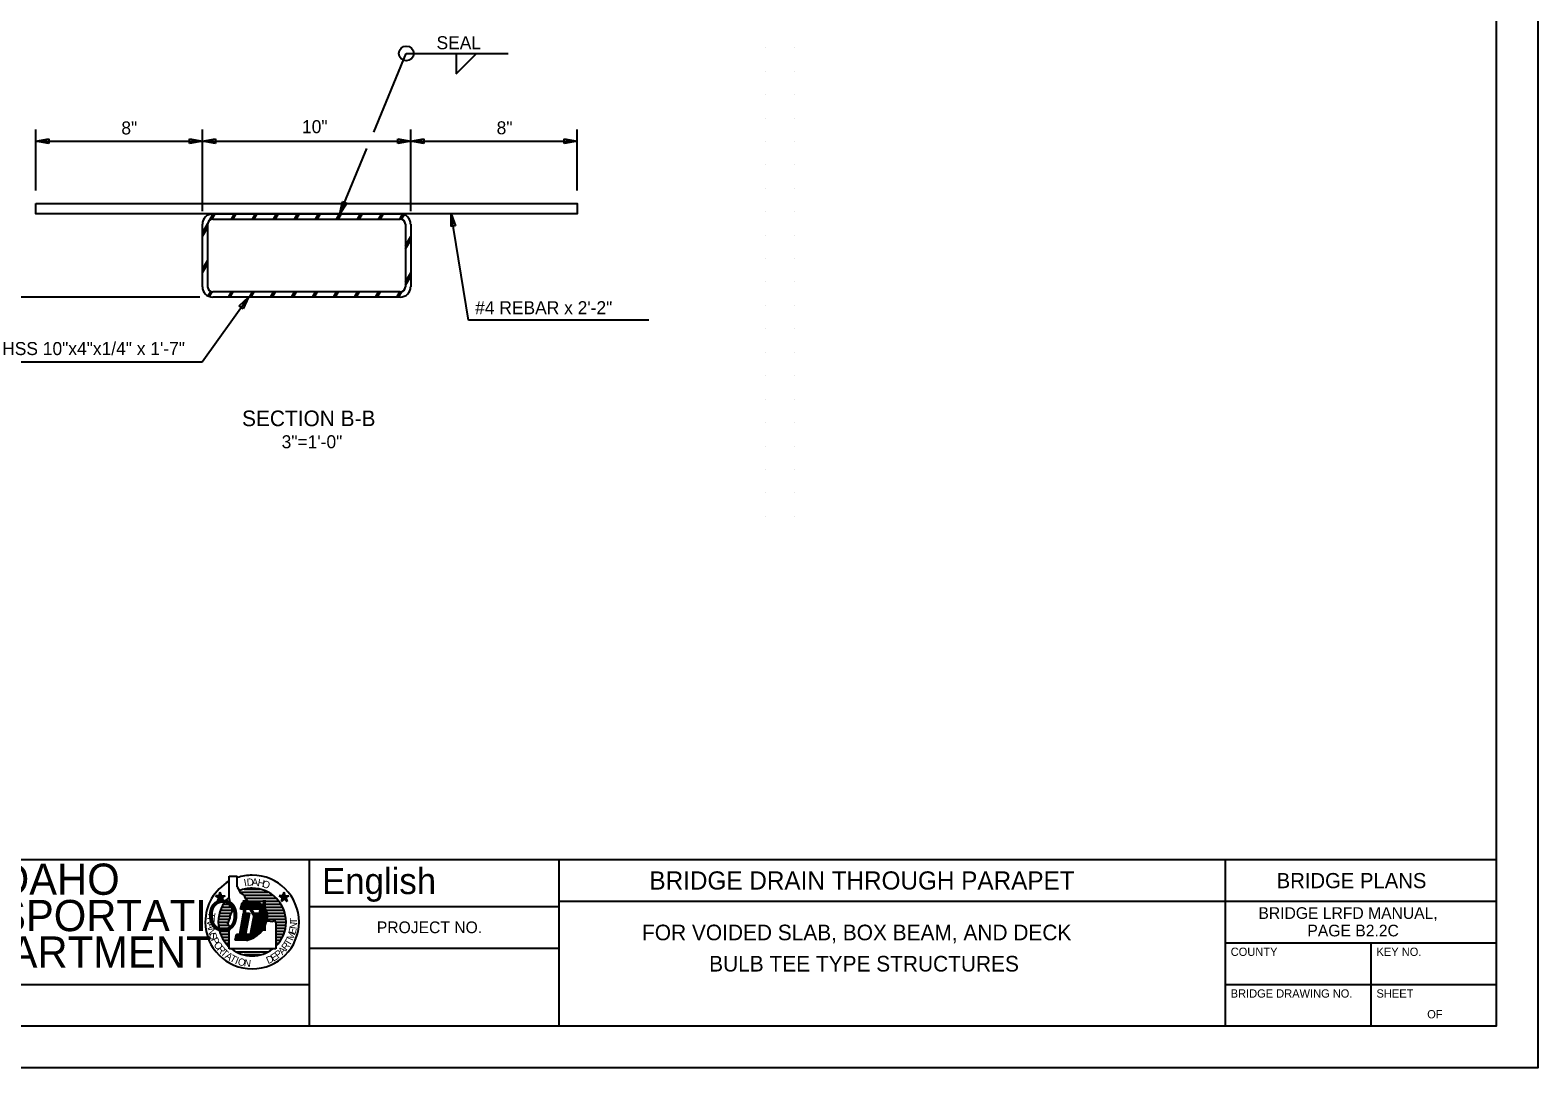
# Model space of a CAD drawing. Extents: x 0 to 22.7, y 0 to 15.7.
# Drawn here: x 10.6 to 22.67, y 0 to 8.31 of the extents above; entities that cross this region are included whole.
import ezdxf

# ---------------------------------------------------------------- set-up
doc = ezdxf.new("R2010")
doc.units = 0
for name, color, linetype in [('BORDER_ANNO_Cutsheet', 7, 'Continuous'), ('BRDG_ANNO_Anno-Sheet', 7, 'Continuous'), ('BRDG_ANNO_General-Notes', 7, 'Continuous'), ('BRDG_BASE_Active-Point', 7, 'Continuous'), ('BRDG_BASE_Obj-Line', 7, 'Continuous'), ('BRDG_BASE_Pattern', 7, 'Continuous'), ('BRDG_BASE_Rebar', 7, 'Continuous'), ('Default', 7, 'Continuous')]:
    doc.layers.add(name, color=color, linetype=linetype)

# ---------------------------------------------------------------- blocks, each defined once
blk = doc.blocks.new('TERM')
at = {"layer": 'Default'}
for p, q in [((-1.6, -0.27), (-1.6, 0.27)), ((-1.6, 0.27), (0, 0)), ((0, 0), (-1.6, -0.27))]:
    blk.add_line(p, q, dxfattribs=at)

msp = doc.modelspace()

# ---------------------------------------------------------------- linework, layer by layer
at = {"layer": 'BORDER_ANNO_Cutsheet'}
msp.add_lwpolyline([(0, 14.667), (22.667, 14.667), (22.667, 0), (0, 0)], close=True, dxfattribs=at)
at = {"layer": 'BRDG_ANNO_Anno-Sheet'}
for p, q in [((1, 1.667), (12.833, 1.667)), ((12.833, 0.333), (12.833, 1.667)), ((12.833, 1.667), (22.333, 1.667)), ((14.833, 0.333), (14.833, 1.667)), ((20.167, 0.333), (20.167, 1.667)), ((12.19, 1.362), (12.19, 1.535)), ((12.19, 1.535), (12.255, 1.535)), ((12.255, 1.449), (12.255, 1.535)), ((12.255, 1.449), (12.273, 1.417)), ((12.134, 1.36), (12.082, 1.377)), ((12.11, 1.377), (12.082, 1.377)), ((12.105, 1.36), (12.082, 1.377)), ((12.129, 1.377), (12.096, 1.332)), ((12.105, 1.36), (12.096, 1.332)), ((12.12, 1.349), (12.096, 1.332)), ((12.105, 1.36), (12.158, 1.377)), ((12.11, 1.377), (12.12, 1.405)), ((12.11, 1.377), (12.143, 1.332)), ((12.12, 1.349), (12.12, 1.405)), ((12.129, 1.377), (12.12, 1.405)), ((12.12, 1.349), (12.143, 1.332)), ((12.129, 1.377), (12.158, 1.377)), ((12.134, 1.36), (12.158, 1.377)), ((12.134, 1.36), (12.143, 1.332)), ((12.161, 1.334), (12.196, 1.334)), ((12.183, 1.357), (12.191, 1.357)), ((12.196, 1.337), (12.19, 1.362)), ((12.196, 1.317), (12.196, 1.337)), ((12.273, 1.417), (12.276, 1.403)), ((12.276, 1.403), (12.311, 1.379)), ((12.278, 1.405), (12.5, 1.405)), ((12.31, 1.43), (12.439, 1.43)), ((12.31, 1.382), (12.538, 1.382)), ((12.311, 1.379), (12.322, 1.351)), ((12.319, 1.357), (12.567, 1.357)), ((12.322, 1.351), (12.356, 1.324)), ((12.344, 1.334), (12.588, 1.334)), ((12.645, 1.36), (12.592, 1.377)), ((12.616, 1.36), (12.592, 1.377)), ((12.621, 1.377), (12.592, 1.377)), ((12.64, 1.377), (12.607, 1.332)), ((12.616, 1.36), (12.607, 1.332)), ((12.63, 1.349), (12.607, 1.332)), ((12.616, 1.36), (12.668, 1.377)), ((12.621, 1.377), (12.63, 1.405)), ((12.621, 1.377), (12.654, 1.332)), ((12.63, 1.349), (12.63, 1.405)), ((12.64, 1.377), (12.63, 1.405)), ((12.63, 1.349), (12.654, 1.332)), ((12.64, 1.377), (12.668, 1.377)), ((12.645, 1.36), (12.668, 1.377)), ((12.645, 1.36), (12.654, 1.332)), ((14.833, 1.333), (20.167, 1.333)), ((20.167, 1.333), (22.333, 1.333)), ((12.108, 1.214), (12.199, 1.214)), ((12.114, 1.238), (12.207, 1.238)), ((12.121, 1.262), (12.213, 1.262)), ((12.131, 1.285), (12.199, 1.285)), ((12.145, 1.31), (12.195, 1.31)), ((12.196, 1.299), (12.196, 1.317)), ((12.2, 1.285), (12.196, 1.299)), ((12.214, 1.278), (12.2, 1.285)), ((12.2, 1.219), (12.207, 1.233)), ((12.2, 1.202), (12.2, 1.219)), ((12.207, 1.233), (12.214, 1.25)), ((12.214, 1.261), (12.214, 1.278)), ((12.214, 1.25), (12.214, 1.261)), ((12.276, 1.07), (12.307, 1.237)), ((12.277, 1.021), (12.318, 1.237)), ((12.283, 1.271), (12.294, 1.324)), ((12.441, 1.271), (12.283, 1.271)), ((12.288, 1.021), (12.329, 1.237)), ((12.293, 1.271), (12.303, 1.324)), ((12.294, 1.324), (12.408, 1.324)), ((12.299, 1.021), (12.339, 1.237)), ((12.303, 1.271), (12.313, 1.324)), ((12.307, 1.237), (12.353, 1.237)), ((12.31, 1.021), (12.35, 1.237)), ((12.314, 1.271), (12.324, 1.324)), ((12.353, 1.237), (12.322, 1.07)), ((12.325, 1.271), (12.335, 1.324)), ((12.335, 1.271), (12.345, 1.324)), ((12.346, 1.271), (12.355, 1.324)), ((12.356, 1.271), (12.366, 1.324)), ((12.362, 1.07), (12.394, 1.237)), ((12.365, 1.032), (12.403, 1.237)), ((12.367, 1.271), (12.377, 1.324)), ((12.376, 1.037), (12.413, 1.237)), ((12.377, 1.271), (12.387, 1.324)), ((12.387, 1.042), (12.424, 1.237)), ((12.388, 1.271), (12.398, 1.324)), ((12.394, 1.237), (12.435, 1.237)), ((12.399, 1.271), (12.409, 1.324)), ((12.4, 1.05), (12.448, 1.308)), ((12.409, 1.271), (12.419, 1.321)), ((12.412, 1.057), (12.457, 1.301)), ((12.42, 1.271), (12.429, 1.318)), ((12.424, 1.067), (12.466, 1.292)), ((12.43, 1.271), (12.438, 1.313)), ((12.435, 1.237), (12.441, 1.271)), ((12.437, 1.079), (12.475, 1.283)), ((12.446, 1.31), (12.605, 1.31)), ((12.45, 1.093), (12.483, 1.271)), ((12.465, 1.113), (12.491, 1.255)), ((12.473, 1.285), (12.618, 1.285)), ((12.481, 1.145), (12.497, 1.23)), ((12.488, 1.262), (12.629, 1.262)), ((12.496, 1.238), (12.636, 1.238)), ((12.498, 1.214), (12.642, 1.214)), ((12.833, 1.292), (14.833, 1.292)), ((12.104, 1.165), (12.185, 1.165)), ((12.105, 1.19), (12.194, 1.19)), ((12.105, 1.142), (12.188, 1.142)), ((12.109, 1.117), (12.199, 1.117)), ((12.114, 1.094), (12.189, 1.094)), ((12.179, 1.15), (12.186, 1.167)), ((12.19, 1.14), (12.179, 1.15)), ((12.186, 1.167), (12.19, 1.181)), ((12.19, 1.181), (12.2, 1.202)), ((12.196, 1.129), (12.19, 1.14)), ((12.19, 1.101), (12.2, 1.112)), ((12.19, 0.952), (12.19, 1.101)), ((12.2, 1.122), (12.196, 1.129)), ((12.2, 1.112), (12.2, 1.122)), ((12.494, 1.185), (12.499, 1.177)), ((12.495, 1.19), (12.645, 1.19)), ((12.499, 1.177), (12.52, 1.174)), ((12.52, 1.174), (12.54, 1.171)), ((12.54, 1.171), (12.551, 1.185)), ((12.551, 1.185), (12.565, 1.164)), ((12.563, 1.165), (12.646, 1.165)), ((12.565, 1.164), (12.565, 0.952)), ((12.565, 1.142), (12.645, 1.142)), ((12.565, 1.117), (12.641, 1.117)), ((12.565, 1.094), (12.636, 1.094)), ((12.122, 1.07), (12.188, 1.07)), ((12.133, 1.045), (12.188, 1.045)), ((12.147, 1.022), (12.189, 1.022)), ((12.164, 0.997), (12.188, 0.997)), ((12.185, 0.974), (12.189, 0.974)), ((12.24, 1.021), (12.249, 1.07)), ((12.328, 1.021), (12.24, 1.021)), ((12.246, 1.021), (12.255, 1.07)), ((12.249, 1.07), (12.276, 1.07)), ((12.257, 1.021), (12.266, 1.07)), ((12.267, 1.021), (12.276, 1.07)), ((12.32, 1.021), (12.329, 1.07)), ((12.322, 1.07), (12.362, 1.07)), ((12.331, 1.022), (12.34, 1.07)), ((12.342, 1.025), (12.35, 1.07)), ((12.353, 1.028), (12.361, 1.07)), ((12.565, 1.07), (12.627, 1.07)), ((12.565, 1.045), (12.617, 1.045)), ((12.565, 1.022), (12.603, 1.022)), ((12.565, 0.997), (12.587, 0.997)), ((20.167, 1), (22.333, 1)), ((21.333, 0.333), (21.333, 1)), ((12.565, 0.952), (12.19, 0.952)), ((12.5, 0.927), (12.248, 0.927)), ((12.439, 0.904), (12.312, 0.904)), ((12.833, 0.958), (14.833, 0.958)), ((9.333, 0.667), (12.833, 0.667)), ((20.167, 0.667), (22.333, 0.667))]:
    msp.add_line(p, q, dxfattribs=at)
msp.add_lwpolyline([(1, 14.333), (22.333, 14.333), (22.333, 0.333), (1, 0.333)], close=True, dxfattribs=at)
for centre, radius, start, end in [((12.375, 1.167), 0.375, 119.6331, 180), ((12.375, 1.167), 0.375, 90, 108.596), ((12.375, 1.167), 0.375, 0, 90), ((12.375, 1.167), 0.271, 133.1926, 180), ((12.375, 1.167), 0.271, 90, 112.1452), ((12.375, 1.167), 0.271, 0, 90), ((12.389, 1.216), 0.109, 343.4981, 79.7362), ((12.375, 1.167), 0.375, 180, 270), ((12.375, 1.167), 0.271, 180.2644, 226.7946), ((12.29, 1.225), 0.208, 280.6479, 348.7719), ((12.375, 1.167), 0.375, 270, 0), ((12.375, 1.167), 0.271, 314.427, 0), ((12.375, 1.167), 0.271, 232.5658, 270), ((12.375, 1.167), 0.271, 270, 307.4536)]:
    msp.add_arc(centre, radius, start, end, dxfattribs=at)
at = {"layer": 'BRDG_ANNO_General-Notes'}
for p, q in [((13.348, 7.488), (13.609, 8.119)), ((13.609, 8.119), (14.424, 8.119)), ((14.008, 8.119), (14.008, 7.957)), ((14.008, 7.957), (14.171, 8.119)), ((10.644, 7.022), (10.644, 7.511)), ((11.977, 6.856), (11.977, 7.511)), ((13.644, 6.856), (13.644, 7.511)), ((14.977, 7.022), (14.977, 7.511)), ((10.644, 7.417), (11.977, 7.417)), ((11.977, 7.417), (13.644, 7.417)), ((13.644, 7.417), (14.977, 7.417)), ((13.077, 6.835), (13.294, 7.359)), ((13.077, 6.835), (13.098, 6.935)), ((13.133, 6.92), (13.077, 6.835)), ((13.098, 6.935), (13.133, 6.92)), ((13.967, 6.733), (13.969, 6.835)), ((14.108, 5.984), (13.969, 6.835)), ((13.969, 6.835), (14.004, 6.739)), ((14.004, 6.739), (13.967, 6.733)), ((11.956, 6.168), (10.225, 6.168)), ((11.974, 5.65), (12.345, 6.168)), ((12.272, 6.098), (12.345, 6.168)), ((12.345, 6.168), (12.302, 6.076)), ((12.302, 6.076), (12.272, 6.098)), ((15.551, 5.984), (14.108, 5.984)), ((10.393, 5.65), (11.974, 5.65))]:
    msp.add_line(p, q, dxfattribs=at)
msp.add_circle((13.609, 8.119), 0.0592, dxfattribs=at)
at = {"layer": 'BRDG_BASE_Active-Point'}
for p, q in [((16.487, 8.165), (16.487, 8.165)), ((16.716, 8.165), (16.716, 8.165)), ((16.487, 7.977), (16.487, 7.977)), ((16.716, 7.977), (16.716, 7.977)), ((16.487, 7.79), (16.487, 7.79)), ((16.716, 7.79), (16.716, 7.79)), ((16.487, 7.602), (16.487, 7.602)), ((16.716, 7.602), (16.716, 7.602)), ((16.487, 7.415), (16.487, 7.415)), ((16.716, 7.415), (16.716, 7.415)), ((16.487, 7.227), (16.487, 7.227)), ((16.716, 7.227), (16.716, 7.227)), ((16.487, 7.04), (16.487, 7.04)), ((16.716, 7.04), (16.716, 7.04)), ((16.487, 6.852), (16.487, 6.852)), ((16.716, 6.852), (16.716, 6.852)), ((16.487, 6.665), (16.487, 6.665)), ((16.716, 6.665), (16.716, 6.665)), ((16.487, 6.477), (16.487, 6.477)), ((16.716, 6.477), (16.716, 6.477)), ((16.487, 6.29), (16.487, 6.29)), ((16.716, 6.29), (16.716, 6.29)), ((16.487, 6.102), (16.487, 6.102)), ((16.716, 6.102), (16.716, 6.102)), ((16.487, 5.915), (16.487, 5.915)), ((16.716, 5.915), (16.716, 5.915)), ((16.487, 5.727), (16.487, 5.727)), ((16.716, 5.727), (16.716, 5.727)), ((16.487, 5.54), (16.487, 5.54)), ((16.716, 5.54), (16.716, 5.54)), ((16.487, 5.352), (16.487, 5.352)), ((16.716, 5.352), (16.716, 5.352)), ((16.487, 5.165), (16.487, 5.165)), ((16.716, 5.165), (16.716, 5.165)), ((16.487, 4.977), (16.487, 4.977)), ((16.716, 4.977), (16.716, 4.977)), ((16.487, 4.79), (16.487, 4.79)), ((16.716, 4.79), (16.716, 4.79)), ((16.487, 4.602), (16.487, 4.602)), ((16.716, 4.602), (16.716, 4.602)), ((16.487, 4.415), (16.487, 4.415)), ((16.716, 4.415), (16.716, 4.415))]:
    msp.add_line(p, q, dxfattribs=at)
at = {"layer": 'BRDG_BASE_Obj-Line'}
for p, q in [((12.06, 6.835), (13.56, 6.835)), ((12.06, 6.793), (13.56, 6.793)), ((11.977, 6.252), (11.977, 6.752)), ((12.019, 6.252), (12.019, 6.752)), ((13.602, 6.752), (13.602, 6.252)), ((13.644, 6.752), (13.644, 6.252)), ((13.56, 6.21), (12.06, 6.21)), ((13.56, 6.168), (12.06, 6.168))]:
    msp.add_line(p, q, dxfattribs=at)
for centre, radius, start, end in [((12.06, 6.752), 0.0833, 90, 180), ((12.06, 6.752), 0.0417, 90, 180), ((13.56, 6.752), 0.0833, 0, 90), ((13.56, 6.752), 0.0417, 0, 90), ((12.06, 6.252), 0.0833, 180, 270), ((12.06, 6.252), 0.0417, 180, 270), ((13.56, 6.252), 0.0833, 270, 360), ((13.56, 6.252), 0.0417, 270, 360)]:
    msp.add_arc(centre, radius, start, end, dxfattribs=at)
at = {"layer": 'BRDG_BASE_Pattern'}
for p, q in [((11.977, 6.683), (12.021, 6.759)), ((12.034, 6.782), (12.064, 6.835)), ((12.054, 6.792), (12.079, 6.835)), ((12.209, 6.793), (12.233, 6.835)), ((12.224, 6.793), (12.248, 6.835)), ((12.377, 6.793), (12.401, 6.835)), ((12.392, 6.793), (12.416, 6.835)), ((12.546, 6.793), (12.57, 6.835)), ((12.561, 6.793), (12.585, 6.835)), ((12.714, 6.793), (12.738, 6.835)), ((12.729, 6.793), (12.753, 6.835)), ((12.882, 6.793), (12.906, 6.835)), ((12.897, 6.793), (12.921, 6.835)), ((13.051, 6.793), (13.075, 6.835)), ((13.066, 6.793), (13.09, 6.835)), ((13.219, 6.793), (13.243, 6.835)), ((13.234, 6.793), (13.258, 6.835)), ((13.387, 6.793), (13.412, 6.835)), ((13.402, 6.793), (13.427, 6.835)), ((13.556, 6.793), (13.578, 6.832)), ((13.569, 6.791), (13.591, 6.828)), ((11.977, 6.658), (12.019, 6.73)), ((13.602, 6.581), (13.644, 6.654)), ((13.602, 6.555), (13.644, 6.628)), ((11.977, 6.392), (12.019, 6.464)), ((11.977, 6.366), (12.019, 6.438)), ((13.602, 6.29), (13.644, 6.362)), ((13.602, 6.264), (13.644, 6.336)), ((12.022, 6.178), (12.043, 6.215)), ((12.034, 6.174), (12.056, 6.211)), ((12.185, 6.168), (12.209, 6.21)), ((12.2, 6.168), (12.224, 6.21)), ((12.353, 6.168), (12.377, 6.21)), ((12.368, 6.168), (12.392, 6.21)), ((12.521, 6.168), (12.546, 6.21)), ((12.536, 6.168), (12.561, 6.21)), ((12.69, 6.168), (12.714, 6.21)), ((12.705, 6.168), (12.729, 6.21)), ((12.858, 6.168), (12.882, 6.21)), ((12.873, 6.168), (12.897, 6.21)), ((13.027, 6.168), (13.051, 6.21)), ((13.042, 6.168), (13.066, 6.21)), ((13.195, 6.168), (13.219, 6.21)), ((13.21, 6.168), (13.234, 6.21)), ((13.363, 6.168), (13.387, 6.21)), ((13.378, 6.168), (13.402, 6.21)), ((13.532, 6.168), (13.556, 6.21)), ((13.547, 6.168), (13.573, 6.213))]:
    msp.add_line(p, q, dxfattribs=at)
at = {"layer": 'BRDG_BASE_Rebar'}
msp.add_lwpolyline([(10.644, 6.918), (14.977, 6.918), (14.977, 6.835), (10.644, 6.835)], close=True, dxfattribs=at)

# ---------------------------------------------------------------- block references
at = {"layer": 'BRDG_ANNO_General-Notes', "xscale": 0.06510416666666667, "yscale": 0.0732421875, "rotation": 180}
for p in [(10.644, 7.417), (11.977, 7.417), (13.644, 7.417)]:
    msp.add_blockref('TERM', p, dxfattribs=at)
at = {"layer": 'BRDG_ANNO_General-Notes', "xscale": 0.06510416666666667, "yscale": 0.0732421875}
for p in [(11.977, 7.417), (13.644, 7.417), (14.977, 7.417)]:
    msp.add_blockref('TERM', p, dxfattribs=at)

# ---------------------------------------------------------------- texts
at = {"layer": 'BRDG_ANNO_Anno-Sheet'}
for s, height, p in [('IDAHO', 0.25, (10.256, 1.385)), ('English', 0.2083, (12.934, 1.391)), ('BRIDGE DRAIN THROUGH PARAPET', 0.14542, (15.555, 1.427)), ('BRIDGE PLANS', 0.12125, (20.576, 1.438)), ('TRANSPORTATION', 0.25, (9.431, 1.094)), ('BRIDGE LRFD MANUAL,', 0.09375, (20.43, 1.192)), ('PROJECT NO.', 0.09375, (13.373, 1.078)), ('FOR VOIDED SLAB, BOX BEAM, AND DECK', 0.125, (15.496, 1.021)), ('PAGE B2.2C', 0.0938, (20.822, 1.052)), ('DEPARTMENT', 0.25, (9.746, 0.802)), ('BULB TEE TYPE STRUCTURES', 0.125, (16.033, 0.771)), ('COUNTY', 0.0663, (20.208, 0.896)), ('KEY NO.', 0.0663, (21.375, 0.896)), ('BRIDGE DRAWING NO.', 0.06625, (20.208, 0.562)), ('SHEET', 0.0663, (21.375, 0.562)), ('OF', 0.0663, (21.781, 0.396))]:
    msp.add_text(s, height=height, dxfattribs=at).set_placement(p)
for s, rotation, p in [('I', 11.9519, (12.315, 1.452)), ('D', 5.2118, (12.334, 1.456)), ('A', 357.8718, (12.371, 1.459)), ('H', 349.6318, (12.415, 1.456)), ('O', 342.1917, (12.45, 1.449)), ('T', 259.4265, (12.025, 1.25)), ('R', 266.0275, (12.018, 1.205)), ('A', 273.764, (12.015, 1.16)), ('N', 280.3758, (12.019, 1.114)), ('M', 67.7139, (12.7, 1.014)), ('E', 75.6105, (12.72, 1.065)), ('N', 83.1932, (12.73, 1.109)), ('T', 90.4926, (12.735, 1.153)), ('S', 287.9279, (12.029, 1.069)), ('P', 295.4976, (12.044, 1.027)), ('O', 302.6446, (12.064, 0.987)), ('R', 309.9079, (12.089, 0.948)), ('R', 52.3344, (12.649, 0.934)), ('T', 59.0362, (12.676, 0.97)), ('T', 317.1211, (12.118, 0.914)), ('A', 324.6375, (12.152, 0.884)), ('T', 331.7503, (12.19, 0.858)), ('I', 337.0213, (12.233, 0.836)), ('O', 343.3287, (12.255, 0.827)), ('N', 351.6598, (12.306, 0.813)), ('D', 22.9887, (12.502, 0.83)), ('E', 30.5476, (12.544, 0.849)), ('P', 37.6656, (12.582, 0.873)), ('A', 45, (12.617, 0.9))]:
    msp.add_text(s, height=0.0579, rotation=rotation, dxfattribs=at).set_placement(p)
at = {"layer": 'BRDG_ANNO_General-Notes'}
for s, height, p in [('SEAL', 0.1042, (13.851, 8.153)), ('8"', 0.1042, (11.328, 7.471)), ('10"', 0.1042, (12.774, 7.481)), ('8"', 0.1042, (14.332, 7.472)), ('#4 REBAR x 2\'-2"', 0.10417, (14.16, 6.032)), ('HSS 10"x4"x1/4" x 1\'-7"', 0.10417, (10.374, 5.705)), ('SECTION B-B', 0.125, (12.294, 5.136)), ('3"=1\'-0"', 0.1042, (12.611, 4.959))]:
    msp.add_text(s, height=height, dxfattribs=at).set_placement(p)

doc.saveas('drawing.dxf')
